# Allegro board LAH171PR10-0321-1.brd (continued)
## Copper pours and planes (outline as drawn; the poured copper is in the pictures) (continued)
GNDA on VCC: 297.22,28.78 296.58,29.41 295.69,29.41 294.64,30.47 294.64,40.18 290.55,44.27 287.37,44.27 286.7,44.95 286.7,46.28 286.23,46.75 282.8,46.75 282.25,47.3 282.25,50.53 282.14,50.65 282.31,50.81 283.64,50.81 284.16,51.33 284.16,52.28 284.21,52.33 287.51,52.33 287.71,52.54 287.71,54.5 287.89,54.68 289.48,54.68 290.56,55.76 292.21,55.76 292.73,56.28 292.73,58.36 292.4,58.68 290.77,58.68 290.39,58.3 289.38,58.3 287.53,56.46 286.69,56.46 286.51,56.64 286.51,57.93 287.08,58.5 287.08,59.77 287.83,60.53 288.01,60.53 288.07,60.59 288.84,60.59 289.47,61.22 292.88,61.22 293.94,60.17 293.94,44.8 298.02,40.71 305.05,40.71 305.98,40.43 306.91,40.71 308.18,40.71 308.63,40.27 314.85,40.27 315.11,39.93 315.46,39.67 309.88,39.67 309.81,39.6 309.81,39.14 309.51,38.83 308.26,38.83 307.96,39.14 307.96,39.57 307.86,39.67 305.35,39.67 303.8,38.63 304.18,36.81 304.18,32.39 303.78,30.62 305.24,29.53 305.32,29.61 305.32,30.05 305.65,30.38 306.89,30.38 307.17,30.1 307.17,29.63 307.27,29.53 317.08,29.53 317.08,28.78
VCC2_IA on BOTTOM: 170.56,131.65 169.98,131.65 169.92,131.58 169.92,131.01 170.24,130.69 170.24,130.5 170.43,130.31 170.43,129.49 170.49,129.42 170.75,129.42 170.81,129.49 170.81,130.12 170.75,130.19 170.75,131.46
VCC3_IA on BOTTOM: 179.26,133.36 178.24,133.36 178.18,133.3 178.18,132.09 178.3,131.96 179.26,131.96 179.57,131.65 179.57,131.14 180.4,130.31 180.4,129.61 180.46,129.55 180.65,129.55 180.72,129.61 180.72,130.69 180.46,130.95 180.46,132.22 180.21,132.47 179.51,132.47 179.38,132.6 179.38,133.23
VCC4_IA on BOTTOM: 190.37,130.95 190.37,129.68 190.3,129.61 190.11,129.61 190.05,129.68 190.05,131.9 189.8,132.15 188.91,132.15 188.84,132.22 188.84,133.36 188.91,133.42 189.92,133.42 190.05,133.3 190.05,132.47 190.11,132.41 190.81,132.41 190.88,132.34 190.88,131.46
VCC_1.05VALWP on BOTTOM (solid shape): 198.05,88.59 198.05,87.44 197.94,87.32 197.18,87.32 197.1,87.4 197.1,87.94 197.24,88.07 197.24,88.35 197.54,88.66 197.99,88.66
VCC_GT on BOTTOM: 100.07,86.37 99.5,86.37 99.44,86.31 99.06,86.31 98.74,85.99 97.47,85.99 97.4,85.93 97.4,85.23 97.21,85.04 96.45,85.04 96.39,84.97 96.39,84.15 96.45,84.08 97.4,84.08 97.47,84.15 97.47,84.59 98.48,85.61 98.86,85.61 99.31,86.05 100.13,86.05 100.2,86.12 100.2,86.24
VCC_SA on BOTTOM: 193.1,121.61 195.58,121.61 196.08,121.1 197.73,121.1 197.99,120.85 197.99,119.14 197.92,119.07 197.8,119.07 197.73,119.14 197.73,120.41 197.54,120.6 195,120.6 194.94,120.53 193.42,120.53 193.04,120.91 193.04,121.55
VDD_CHG on BOTTOM (solid shape): 128.03,38.3 128.03,37.92 127.87,37.77 127.67,37.77 127.57,37.67 126.4,37.67 126.35,37.72 126.35,37.82 126.4,37.87 127.19,37.87 127.72,38.4 127.93,38.4
VDD_CHG on TOP: 139.31,36.08 141.66,36.08 141.79,35.95 141.79,35.32 141.54,35.06 139.12,35.06 139,35.19 139,35.76
VDDP_CHG on BOTTOM (solid shape): 121.9,40.44 121.9,40.32 121.9,40.32 121.9,39.3 121.89,39.29 121.89,38.81 122.43,38.27 123.09,38.27 123.14,38.22 123.14,38.1 123.09,38.05 122.15,38.05 121.46,38.73 121.07,38.73 121,38.8 121,40.57 121.77,40.57
VIN_1.2V_RUN on BOTTOM (solid shape): 270.1,68 270.61,68 270.61,68.58 271.24,68.58 271.44,68.39 271.44,66.61 271.24,66.42 269.78,66.42 269.15,65.78 268.83,65.78 268.64,65.97 268.64,67.45 268.98,67.45 269.67,68.14 269.67,68.58 270.1,68.58
VIN_1.8VALW on TOP (solid shape): 229.92,73.15 229.92,71.07 229.79,70.94 227.87,70.94 227.87,71.35 227.87,71.35 227.32,71.35 227.31,71.36 227.31,71.53 227.32,71.54 227.86,71.54 227.87,71.54 227.87,71.66 227.87,71.96 229.24,73.33 229.73,73.33
VIN_1VS_VCCIO on TOP: 199.39,96.47 199.7,96.15 201.16,96.15 201.29,96.28 201.29,99.77 200.97,100.09 199.7,100.09 199.39,99.77
VIN_1VS_VCCIO on BOTTOM: 198.94,98.31 200.21,98.31 200.59,98.69 201.1,98.69 201.29,98.5 201.29,97.86 201.48,97.67 201.48,96.72 200.91,96.15 200.91,95.51 201.48,95.51 201.48,95.39 200.91,95.39 200.91,94.94 200.85,94.88 200.46,94.88 198.81,96.53 198.81,98.18
VIN_2.5V_MEM on TOP: 149.86,38.26 151.19,38.26 151.38,38.07 151.38,37.39 151.95,37.39 151.95,37.26 151.38,37.26 151.38,36.68 151.07,36.37 150.76,36.37 150.5,36.12 150.5,35.58 150.45,35.53 149.28,35.53 149.16,35.66 149.16,36.04 149.73,36.61 149.73,38.14
+BL_PWR_SRC on BOTTOM (solid shape): 134.74,132.73 134.74,132.23 134.5,131.98 134.27,131.98 133.93,131.65 133.93,130.47 133.85,130.39 132.68,130.39 132.6,130.47 132.6,131.75 132.14,132.21 132.14,132.65 132.27,132.78 134.69,132.78
+BL_PWR_SRC on TOP: 142.87,126.38 142.24,127.01 140.9,127.01 139.12,128.79 137.22,128.79 135.89,130.12 133.03,130.12 132.52,130.63 132.52,132.28 132.65,132.41 133.47,132.41 133.67,132.6 133.67,133.61 133.79,133.73 135.58,133.73 135.63,133.68 135.63,132.47 136.46,131.65 137.35,131.65 138.17,130.82 140.14,130.82 141.73,129.23 143.76,129.23 144.2,128.79 144.2,127.65 143.76,127.2 143.76,126.57 143.57,126.38
+BL_PWR_SRC_P on TOP (solid shape): 134.95,136.74 134.95,136.09 135.5,135.54 135.5,134.57 135.3,134.37 134.01,134.37 133.47,133.83 133.47,132.79 133.28,132.6 132.08,132.6 131.83,132.85 131.83,136.57 132.06,136.8 134.88,136.8
+EDP_VDD on TOP: 145.92,132.73 147.63,132.73 147.7,132.66 147.7,131.2 147.44,130.95 145.92,130.95 145.85,131.01 145.85,131.52 145.28,131.52 145.28,131.65 145.85,131.65 145.85,132.66
+GT_CORE on BOTTOM (solid shape): 147.48,92.65 147.53,92.64 147.57,92.6 147.61,92.34 147.83,92.19 147.86,92.18 147.92,92.18 148.1,92 148.1,91.86 148.07,91.8 148.05,91.74 148,91.68 147.92,91.67 147.67,91.62 147.52,91.4 147.49,91.34 147.42,91.32 147.39,91.32 147.32,91.34 147.28,91.4 146.96,91.67 146.63,91.4 146.6,91.34 146.53,91.32 146.49,91.32 146.45,91.32 146.37,91.33 146.33,91.4 146.01,91.67 145.68,91.4 145.65,91.35 145.58,91.32 145.55,91.32 145.48,91.34 145.44,91.4 145.33,91.6 145.12,91.67 145.09,91.67 145.04,91.72 145.1,91.78 145.1,92.15 145.12,92.18 145.16,92.2 145.2,92.17 145.21,92.16 145.61,92.07 145.79,92.44 145.8,92.53 145.79,92.61 145.82,92.64 145.86,92.65
+GT_CORE on TOP: 115.69,99.07 110.37,99.07 110.08,98.78 110.08,88.94 110.42,88.59 116.2,88.59 117.77,90.16 117.77,91.47 118.07,91.77 118.07,92.15 116.01,94.21 116.01,98.75
+GT_CORE on TOP: outline of 89 points within 133.31,91.06 148.25,109.87
+GT_CORE on BOTTOM: outline of 159 points within 111.95,83.7 148.5,118.95
+GT_CORE on BOTTOM: 141.73,91.24 141.72,91.23 141.66,91.23 141.49,91.06 141.47,91.06 141.24,90.99 141.12,90.79 141.11,90.75 140.89,90.75 140.88,90.78 140.56,91.03 140.24,90.78 140.23,90.75 140,90.75 139.99,90.78 139.95,90.87 139.89,90.95 139.89,91.79 139.47,92.21 139.47,92.55 139.57,92.65 144.47,92.65 144.51,92.64 144.55,92.61 144.54,92.54 144.55,92.47 144.55,92.3 144.64,92.15 144.64,91.97 144.39,91.75 144.51,91.44 144.55,91.35 144.51,91.27 144.44,91.21 144.4,91.13 144.35,91.07 144.28,91.06 144.05,91.02 143.9,90.83 143.9,90.82 143.82,90.75 143.63,90.75 143.62,90.78 143.32,91.03 142.99,90.82 142.99,90.81 142.93,90.75 142.77,90.75 142.66,90.85 142.65,90.85 142.64,90.87 142.5,90.96 142.34,90.97 142.26,90.99 142.22,91.06 142.19,91.16 142.13,91.24 142.13,91.47 142.21,91.59 142.22,91.72 142.22,91.73 141.79,91.94 141.73,91.47
+GT_CORE on IN1: 132.59,109.75 148.29,109.75 148.29,102.93 147.61,102.24 147.61,99.11 146.85,98.35 146.85,97.45 148.29,96.01 148.29,92.59 148.04,92.34 144.06,92.34 143.49,91.77 139.1,91.77 138.91,91.58 137.52,91.58 136.94,92.15 135.12,92.15 134.49,92.78 133.45,92.78 133.33,92.91 133.33,93.29 133.45,93.42 133.86,93.42 134.7,94.26 135.78,94.26 137.56,96.04 137.56,99.43 135.95,101.04 135.95,103.01 134.81,104.15 134.29,104.15 132.4,106.05 132.4,109.56
+GT_CORE on VCC: 112.33,88.19 111.64,88.88 111.64,99.59 115.76,99.59 126.1,109.93 148.62,109.93 148.62,106.61 148.19,106.17 148.19,102.82 147.61,102.24 147.61,99.11 146.85,98.35 146.85,97.45 148.19,96.11 148.19,91.69 120.38,91.69 116.87,88.19
+GT_CORE on IN2: 148.39,110.39 148.39,103.09 147.62,102.32 147.62,99.1 146.85,98.33 146.85,97.45 148.2,96.1 148.2,92.34 147.51,91.64 124.72,91.64 122.31,89.23 118.11,89.23 117.15,88.28 112.26,88.28 111.56,88.97 111.56,96.88 115.66,100.98 115.66,102.59 120.52,107.45 121.92,107.45 126.54,112.08 146.71,112.08
+GT_CORE on IN3: 124.52,109.87 113.91,99.26 113.91,93.61 111.82,91.51 111.82,88.59 112.26,88.15 121.92,88.15 122.55,88.78 122.55,91.77 123.57,92.78 129.66,92.78 130.04,93.16 133.09,93.16 133.47,92.78 139.57,92.78 139.95,92.4 147.51,92.4 148.18,93.08 148.18,96.12 146.84,97.46 146.84,98.33 147.61,99.1 147.61,102.24 148.33,102.96 148.33,109.61 148.08,109.87
+GT_CORE on IN4: 124.52,109.87 113.91,99.26 113.91,93.61 111.82,91.51 111.82,88.59 112.26,88.15 121.92,88.15 126.17,92.4 134.55,92.4 135.25,91.7 147.25,91.7 147.63,92.09 147.63,92.66 147.44,92.85 145.54,92.85 145.09,93.29 145.09,94.12 145.92,94.94 148.08,94.94 148.2,95.06 148.2,96.1 146.85,97.45 146.85,98.35 147.61,99.11 147.61,102.24 148.19,102.82 148.19,106.17 148.33,106.31 148.33,109.61 148.08,109.87
+IA_CORE on TOP (solid shape): 167.69,94.04 167.69,93.58 167.96,93.31 167.96,92.82 168.02,92.4 168.44,92.34 168.47,92.31 168.47,91.92 168.49,91.91 168.49,90.52 168.42,90.45 168.37,90.45 167.53,90.45 167.47,90.52 167.47,91.6 167.17,91.89 167.17,92.48 167.06,92.59 167.06,94.06 167.13,94.12 167.61,94.12
+IA_CORE on TOP: outline of 174 points within 147.35,90.33 187.19,124.72 ; 3 cut-outs
+IA_CORE on BOTTOM: outline of 101 points within 160.45,90.75 168.89,92.73
+IA_CORE on BOTTOM: outline of 376 points within 148.66,102.94 190.94,122.57
+IA_CORE on BOTTOM: outline of 131 points within 149.05,90.32 160.69,92.68
+IA_CORE on IN1: 150.6,119.45 163.13,119.45 163.51,119.83 181.95,119.83 184.06,121.94 185.73,121.94 187.13,120.55 187.13,117.96 186.39,117.22 190.69,117.22 191.07,116.84 191.07,115.31 189.62,113.87 176.51,113.87 173.76,116.62 150.52,116.62 150.2,116.94 150.2,119.05
+IA_CORE on IN1: 159.51,91.13 158.81,91.83 149.65,91.83 149.65,91.83 149.45,91.83 149.26,92.02 149.26,92.21 148.63,92.85 148.63,96.39 147.36,97.66 147.36,98.15 148.12,98.91 148.12,102.03 148.63,102.54 148.63,109.74 165.59,109.74 165.59,107.33 165.54,107.25 165.45,107.24 164.95,106.91 165.45,106.59 165.54,106.58 165.59,106.5 165.59,105.4 165.55,105.32 165.47,105.3 165.46,105.3 165.01,104.96 165.46,104.62 165.47,104.62 165.55,104.6 165.59,104.52 165.59,99.32 167.28,97.63 167.28,93.12 168.19,92.21 168.19,91.32 168,91.13
+IA_CORE on VCC: 155.59,90.24 154.14,91.69 148.7,91.69 148.7,96.33 148.68,96.33 147.35,97.66 147.35,98.14 148.12,98.9 148.12,102.03 148.7,102.61 148.7,105.96 149.13,106.39 149.13,122.12 151.61,124.6 184.88,124.6 191.6,117.88 191.6,114.42 189.65,114.42 188.63,115.44 171.43,115.44 165.82,109.83 165.82,99.33 168,97.15 168,92.7 168.33,92.37 168.33,90.24
+IA_CORE on IN2: 149.23,91.08 148.72,91.59 148.72,96.31 147.35,97.68 147.35,98.15 148.12,98.92 148.12,102.02 148.62,102.52 148.62,117.45 153.16,121.99 186.49,121.99 191,117.49 191,115.14 189.61,113.74 177.41,113.74 166.27,102.59 166.27,94.17 168.17,92.26 168.17,91.48 167.77,91.08
+IA_CORE on IN3: 149.98,90.24 148.69,91.54 148.69,96.33 147.35,97.66 147.35,98.14 148.12,98.9 148.12,102.03 148.69,102.61 148.69,109.72 149.22,110.25 165.35,110.25 166.17,109.42 166.17,92.28 164.97,91.07 158.87,91.07 158.05,90.24
+IA_CORE on IN3: 150.87,119.64 181.61,119.64 183.89,121.93 186.37,121.93 187.26,121.04 187.26,118.95 188.72,117.49 190.69,117.49 191,117.17 191,115.9 190.18,115.07 190.11,115.07 189.73,114.69 187.96,114.69 186.05,116.6 150.43,116.6 150.05,116.98 150.05,118.82
+IA_CORE on IN4: 151.09,120.62 183.12,120.62 184.34,121.84 188.88,121.84 191.65,119.07 191.65,115.59 189.92,113.87 177.96,113.87 175.29,116.53 166.94,116.53 166.85,116.62 165.41,116.62 165.3,116.72 160.21,116.72 160.1,116.62 150.7,116.62 150.63,116.69 150.63,120.17
+IA_CORE on IN4: 149.09,94.31 148.7,94.7 148.7,96.31 147.36,97.66 147.36,98.09 147.35,98.14 148.12,98.91 148.12,102.03 148.59,102.5 148.59,109.17 149.28,109.87 165.54,109.87 165.92,109.48 165.92,95.01 165.22,94.31
+LCDVDD on TOP (solid shape): 145.25,134.98 145.25,132.69 145.66,132.28 145.66,131.84 145.09,131.84 145.09,131.33 145.66,131.33 145.66,129.39 145.54,129.26 144.97,129.26 144.78,129.45 144.78,130.67 144.28,131.16 142.15,131.16 142,131.01 139.95,131.01 139.76,131.2 139.76,132.28 139.89,132.42 141.02,132.42 141.61,133.01 141.61,133.15 142.59,134.13 142.59,134.81 142.77,134.99 145.24,134.99
+LCDVDD on BOTTOM (solid shape): 140.9,132.4 140.9,132.03 140.77,131.9 140.04,131.9 139.91,131.77 139.91,130.42 139.87,130.38 139.14,130.38 139.11,130.41 139.11,132.45 139.26,132.59 140.71,132.59
+MIC2-VREFO on TOP (solid shape): 287.98,53.49 289.26,53.49 289.52,53.23 289.52,52.92 289.47,52.87 289.15,52.87 288.77,53.25 287.8,53.25 287.72,53.33 287.72,53.43 287.78,53.5 287.97,53.5
+MIC2-VREFO on IN3 (solid shape): 296.92,33.41 296.92,31.38 296.79,31.25 295.91,31.25 295.71,31.44 295.71,33.47 295.91,33.67 296.67,33.67
+MIC2-VREFO on BOTTOM: 296.73,33.22 296.1,33.22 296.03,33.16 296.03,32.59 295.78,32.33 295.78,31.95 295.97,31.76 295.97,30.68 296.03,30.62 296.67,30.62 296.73,30.68 296.73,31.76 296.92,31.95 296.92,32.33 296.79,32.46 296.79,33.16
+REGCTL_PNP10 on TOP (solid shape): 276.27,110.79 276.27,109.34 276.87,108.75 277.1,108.75 277.55,108.3 277.55,107.73 277.4,107.58 276.15,107.58 276.09,107.65 276.09,107.65 276.05,107.69 276.05,110.77 276.12,110.84 276.22,110.84
+RTC_CELL_PCH on TOP: 280.77,101.38 280.77,100.66 282.61,98.82 282.61,98.19 282.81,98 283.51,98 284.4,98.88 284.4,100.96 284.31,101.05 282.69,101.05 282.31,101.43 280.83,101.43
+RTC_CELL_PCH on TOP: 244.6,109.8 244.03,109.8 243.9,109.67 243.9,109.29 243.84,109.23 243.27,109.23 243.21,109.29 243.21,110.72 243.57,111.08 243.57,112.73 243.64,112.8 244.19,112.8 244.22,112.77 244.26,112.73 244.32,112.7 244.72,112.29 244.72,109.93
+SA_CORE on TOP: 187.64,110.82 187.64,108.4 188.15,107.9 197.29,107.9 197.48,108.09 197.48,110.94 197.23,111.2 188.02,111.2
+SA_CORE on TOP: 166.57,100.05 166.42,100.2 166.42,103.37 166.28,103.51 165.75,103.51 165.65,103.61 165.65,104.21 165.71,104.28 166.15,104.28 166.28,104.4 166.28,106.4 166.18,106.5 166.18,109.75 166.56,110.12 168.4,110.12 168.63,109.89 168.63,106.5 168.43,106.3 168.43,103.46 168.37,103.4 167.36,103.4 167.18,103.22 167.18,102.74 167.11,102.66 167.11,101.34 167.34,101.11 168.11,101.11 168.58,101.59 169.06,101.59 169.11,101.53 169.11,100.43 168.73,100.05
+SA_CORE on BOTTOM: 166.54,103.2 166.32,103.42 166.32,108.81 166.46,108.96 166.49,108.96 166.72,109.06 166.74,109.31 166.73,109.32 166.73,109.72 166.74,109.73 166.76,109.82 166.75,109.92 164.65,112.02 164.65,113.23 164.71,113.29 167.32,113.29 167.93,112.68 167.93,108.4 168.06,108.28 168.38,108.28 168.63,108.02 168.63,105.04 169.01,104.66 169.01,103.96 168.25,103.2
+SA_CORE on BOTTOM: 187.64,110.82 187.64,108.28 187.96,107.96 194.43,107.96 194.5,108.02 194.5,109.1 194.37,109.23 193.48,109.23 193.42,109.29 193.42,110.12 193.54,110.25 194.46,110.25 194.46,111.1 194.43,111.14 187.96,111.14
+SA_CORE on IN1: 166.37,109.62 166.37,102.88 166.47,102.78 167.82,102.78 168.15,103.11 168.15,109.48 167.9,109.74 166.49,109.74
+SA_CORE on VCC: 173.65,100.09 172.31,101.42 170.09,101.42 168.69,102.82 166.33,102.82 166.33,109.62 171.64,114.93 188.42,114.93 189.44,113.92 191.75,113.92 193.51,112.16 193.51,104.52 189.16,104.52 187.64,103 187.64,100.09
+SDREG2 on TOP: 295.97,27.07 296.35,27.07 296.4,27.02 296.4,26.44 296.53,26.31 296.53,24.99 296.35,24.81 295.54,24.81 295.49,24.86 295.49,24.99 295.71,25.22 295.71,25.91 295.94,26.13 295.94,27.05
+TBT_SVR_IND on BOTTOM: 38.13,111.68 38.05,111.6 38.05,111.44 38,111.39 37.78,111.39 37.7,111.47 37.7,111.64 37.62,111.72 37.62,112.17 37.45,112.35 37.44,112.35 37.4,112.4 36.8,112.4 36.45,112.75 35.75,112.75 35.62,112.62 35.62,110.66 35.37,110.4 33.91,110.4 33.59,110.72 33.59,113.96 34.53,114.9 36.49,114.9 37.51,113.88 38.17,113.88 38.17,113.88 38.17,113.54 38.17,113.53 38.17,113.43 38.18,113.41 38.18,113.13 38.32,112.99 38.32,112.13 38.34,112.12 38.34,111.8 38.28,111.75 38.23,111.74 38.18,111.73
+TS_PWR on TOP (solid shape): 126.11,132.41 126.11,130.12 125.79,129.8 124.07,129.8 123.63,130.25 123.63,131.9 123.76,132.03 124.96,132.03 125.41,132.47 126.04,132.47
+TS_PWR_QV8 on TOP (solid shape): 123.69,135.07 123.69,132.41 123.44,132.15 123.44,131.26 122.93,130.76 122.23,130.76 121.98,131.01 121.98,135.27 122.11,135.39 123.38,135.39
+USB_EX2_PWR on BOTTOM (solid shape): 21.05,97.23 21.12,97.2 21.15,97.13 21.19,96.96 21.29,96.84 21.33,96.77 21.31,96.69 21.34,96.2 21.83,96.21 21.9,96.24 21.97,96.21 22,96.19 22.03,96.17 22.03,94.81 22.02,94.82 20.9,94.82 20.89,94.81 20.66,94.81 20.55,94.69 18,94.69 16.87,93.56 15.74,93.56 15.49,93.81 15.49,95.13 17.58,97.23
+USB_EX2_PWR on BOTTOM: 23.11,88.59 24,88.59 24.25,88.34 24.25,86.69 23.74,86.18 22.03,85.42 19.11,85.42 18.85,85.67 18.85,87.7 19.11,87.96 20.19,87.96 20.63,87.51 22.86,87.51 22.98,87.64 22.98,88.47
+USB_EX2_PWR on IN1: 17.84,85.8 17.14,86.5 17.14,91.78 15.46,93.46 15.46,95.27 16.19,96 19.71,96 20.12,95.58 20.12,86.05 19.87,85.8
+USB_EX3_PWR on TOP (solid shape): 301.43,50.68 301.43,47.84 302.12,47.15 302.55,47.15 303.59,46.11 303.59,45.1 303.4,44.9 302.64,44.9 301.94,45.6 299.33,45.6 299.21,45.48 298.31,45.48 298.2,45.58 298.2,46.21 299.27,47.28 299.27,50.68 299.52,50.94 301.18,50.94
+UZ12_TPM on TOP: 246.63,127.65 247.45,127.65 247.9,127.2 250.19,127.2 250.31,127.07 250.31,126.5 250.25,126.44 249.23,126.44 249.04,126.63 248.15,126.63 247.52,127.26 246.69,127.26 246.57,127.39 246.57,127.58
+VHDMI_VCC on TOP: 301.18,82.62 304.1,82.62 304.22,82.5 304.22,81.54 303.91,81.23 303.33,81.23 303.02,81.54 301.24,81.54 301.05,81.73 301.05,82.5
+VHDMI_VCC on TOP: 295.89,81.91 295.89,81.05 295.71,80.87 292.64,80.87 292.54,80.97 292.54,81.99 292.67,82.12 294.06,82.12 294.46,82.51 294.46,82.86 294.85,83.26 296.03,83.26 296.16,83.13 296.16,82.18
+VHDMI_VCC on IN2: 303.14,82.56 303.91,82.56 304.86,81.61 306.13,81.61 306.38,81.35 306.38,80.78 306.19,80.59 303.97,80.59 303.02,81.54 303.02,82.43
+VR_CAP on TOP (solid shape): 261.5,94.67 261.5,94.41 261.38,94.29 261.01,94.29 260.48,93.76 260.03,93.76 259.85,93.58 259.85,93.38 259.75,93.27 259.53,93.27 259.16,93.65 258.77,93.65 258.64,93.78 258.64,94.22 258.77,94.35 259.98,94.35 260.37,94.75 260.71,94.75 260.71,94.75 261.42,94.75
ADP_CHG on BOTTOM (solid shape): 129.28,40.02 129.28,39.13 129.2,39.05 127.1,39.05 126.66,38.6 126.46,38.6 126.24,38.38 126.08,38.38 126.03,38.43 126.03,39.19 126.08,39.24 126.61,39.24 127.01,39.63 128.07,39.63 128.58,40.14 129.15,40.14
AUD_HP_NB_SENSE on IN1 (solid shape): 309.94,30.17 309.94,28.93 309.79,28.78 308.19,28.78 308.08,28.88 308.08,30.15 308.31,30.38 309.74,30.38
AUD_HP_OUT_L1 on BOTTOM (solid shape): 307.22,40.51 307.22,39.06 307.04,38.89 305.39,38.89 305.21,39.06 305.21,40.5 305.3,40.59 307.14,40.59
AUD_HP_OUT_R1 on TOP (solid shape): 312.68,30.25 312.68,29.06 312.48,28.85 310.9,28.85 310.78,28.98 310.78,30.22 310.93,30.38 312.56,30.38
BGATE_CHG on TOP: 115.63,39.32 117.28,39.32 117.41,39.19 117.41,38.17 117.15,37.92 115.82,37.92 115.5,38.24 115.5,39.19
BOOT1_CHG on BOTTOM (solid shape): 124.95,40.69 124.95,39.52 124.66,39.23 124.66,38.43 124.61,38.38 124.48,38.38 124.43,38.43 124.43,39.47 124.52,39.56 124.52,40.28 124.09,40.71 122.99,40.71 122.93,40.78 122.93,41.41 122.99,41.48 124.17,41.48
BOOT2_CHG on BOTTOM (solid shape): 123.14,36.62 123.14,36.5 123.11,36.47 122.17,36.47 121.02,35.32 120.52,35.32 120.46,35.37 120.46,36.34 120.52,36.4 121,36.4 121.44,36.4 121.59,36.55 121.97,36.55 122.1,36.67 123.09,36.67
BS_DDR on TOP: 173.16,39 173.86,39 174.05,38.81 174.05,37.48 173.92,37.35 173.22,37.35 173.1,37.48 173.1,38.94
BS_DDR on BOTTOM: 173.73,39 174.05,38.68 174.05,37.73 173.99,37.67 173.73,37.67 173.29,38.11 173.29,38.94 173.35,39
BS_DDR_R on TOP: 171,38.55 172.52,38.55 172.59,38.49 172.59,37.48 172.46,37.35 170.87,37.35 170.75,37.48 170.75,38.3
BST1_CHG_R on BOTTOM: 123.82,42.94 122.11,42.94 121.92,42.75 121.92,41.98 122.04,41.86 123.69,41.86 123.95,42.11 123.95,42.81
BST2_CHG_R on BOTTOM: 119.15,37 119.98,37 120.14,36.84 120.14,35.25 120.01,35.13 119.47,35.13 119.09,35.51 119.09,36.94
BST2_IA on BOTTOM: 171.51,130.19 171.45,130.12 171.45,129.55 171.51,129.49 171.76,129.49 171.83,129.55 171.83,130.38 171.95,130.5 171.95,131.65 171.89,131.71 171,131.71 170.94,131.65 170.94,131.07 171,131.01 171.45,131.01 171.51,130.95
BST2_IA_R on BOTTOM: 170.97,133.14 170.91,133.07 170.91,132.5 171.35,132.06 172.81,132.06 172.87,132.12 172.87,132.63 172.37,133.14
BST3_IA on BOTTOM: 181.61,131.84 180.65,131.84 180.59,131.77 180.59,131.07 180.65,131.01 181.29,131.01 181.41,130.88 181.41,130.38 181.35,130.31 181.35,129.55 181.41,129.49 181.67,129.49 181.73,129.55 181.73,131.01 181.67,131.07 181.67,131.77
BST3_IA_R on BOTTOM: 180.59,133.17 180.53,133.11 180.53,132.53 180.97,132.09 182.43,132.09 182.49,132.15 182.49,132.66 181.99,133.17
BST4_IA on BOTTOM: 192.02,132.03 191.19,132.03 191.13,131.96 191.13,130.5 191.07,130.44 191.07,129.68 191.13,129.61 191.26,129.61 191.32,129.68 191.32,130.25 192.15,131.07 192.15,131.9
BST4_IA_R on BOTTOM: 192.91,133.36 191.19,133.36 191.13,133.3 191.13,132.34 191.26,132.22 192.97,132.22 193.04,132.28 193.04,133.23
BST_1.05VALWP on BOTTOM (solid shape): 197.2,85.7 197.2,85.04 197.21,85.02 197.21,83.75 197.16,83.7 196.34,83.7 196.27,83.77 196.27,84.46 196.79,84.99 196.79,85.85 196.85,85.9 197,85.9
BST_1.05VALWP_R on BOTTOM (solid shape): 198.05,83 198.05,82.37 197.99,82.31 196.31,82.31 196.26,82.35 196.26,83.02 196.31,83.07 197.99,83.07
BST_3V on BOTTOM: 249.96,47.76 249.96,48.4 249.9,48.46 248.63,48.46 248.5,48.34 247.61,48.34 247.55,48.27 247.55,48.15 247.61,48.08 248.5,48.08 248.88,47.7 249.9,47.7
BST_3V_R on BOTTOM: 249.92,49.1 249.07,49.1 249.01,49.16 249.01,49.83 249.39,50.21 249.39,50.87 249.5,50.98 249.91,50.98 250.02,50.87 250.02,49.2
BST_5V on TOP: 200.34,35.19 201.16,35.19 201.67,34.68 201.67,33.79 201.61,33.73 200.46,33.73 200.21,33.98 200.21,35.06
BST_5V on BOTTOM: 200.02,35.25 200.15,35.25 200.27,35.13 200.72,35.13 200.85,35 200.85,34.17 200.72,34.05 200.15,34.05 199.96,34.24 199.96,35.19
BST_5V_R on TOP: 202.43,35.7 203.07,35.7 203.13,35.63 203.13,33.86 203,33.73 202.43,33.73 202.31,33.86 202.31,35.57
BST_GT on BOTTOM: 100.13,87.32 99.5,87.32 99.44,87.39 98.61,87.39 98.48,87.26 98.04,87.26 97.91,87.13 97.91,86.24 97.98,86.18 98.61,86.18 98.67,86.24 98.67,86.94 98.8,87.07 99.25,87.07 99.31,87.01 100.13,87.01 100.2,87.07 100.2,87.26
BST_GT_R on BOTTOM: 97.34,88.08 96.52,88.08 96.45,88.02 96.45,86.24 96.58,86.12 97.34,86.12 97.47,86.24 97.47,87.96
BST_SA_R on TOP: 200.02,122.69 198.75,122.69 198.69,122.63 198.69,121.93 199.13,121.49 200.59,121.49 200.66,121.55 200.66,122.06
CBP on TOP: 288.54,57.1 288.92,57.1 288.98,57.03 288.98,56.72 288.86,56.59 288.86,56.33 288.6,56.08 287.78,56.08 287.71,56.14 287.71,56.27 287.78,56.33 288.35,56.33 288.48,56.46 288.48,57.03
DCIN_CHG on BOTTOM (solid shape): 127.57,38.78 127.57,38.45 127.16,38.05 126.4,38.05 126.35,38.1 126.35,38.22 126.55,38.43 126.73,38.43 127.21,38.91 127.44,38.91
EN_1.8VALW on TOP (solid shape): 231.8,75.81 231.8,74.82 230.6,73.62 229.12,73.62 228.81,73.31 226.1,73.31 226.04,73.37 226.04,73.95 226.19,74.1 228.63,74.1 228.7,74.17 228.7,74.17 229.08,74.17 229.3,74.39 229.3,74.4 229.57,74.4 229.94,74.08 230.29,74.43 230.92,75.07 230.92,75.71 231.14,75.93 231.68,75.93
FB_1.8VALW on TOP (solid shape): 234.07,75.16 234.07,74.69 233.95,74.57 233.5,74.57 233.24,74.32 233.24,73.01 232.47,72.23 231.18,72.23 231,72.41 231,73.64 232.6,75.24 233.99,75.24
INT_SPK_L+ on TOP (solid shape): 286.25,60.41 286.25,58.63 285.94,58.32 285.94,56.54 285.9,56.51 285.76,56.51 285.7,56.56 285.7,58.59 285.56,58.73 285.56,60.48 286.19,60.48
INT_SPK_L+ on TOP (solid shape): 293.24,36.71 293.24,36.33 292.92,36.01 292.92,35.57 292.86,35.51 292.22,35.51 292.1,35.63 292.1,36.65 292.22,36.78 293.17,36.78
INT_SPK_L+ on IN4 (solid shape): 293.3,36.65 293.3,32.84 293.11,32.65 292.54,32.65 292.1,33.09 292.1,36.65 292.16,36.71 293.24,36.71
INT_SPK_L+ on IN4 (solid shape): 285.49,62.44 285.49,61.55 286.32,60.73 286.32,58.76 286.25,58.7 285.68,58.7 285.55,58.82 285.55,60.48 284.48,61.55 284.48,62.38 284.79,62.7 285.24,62.7
INT_SPK_L- on TOP (solid shape): 290.77,36.14 290.77,35.38 290.65,35.25 289.76,35.25 289.63,35.38 289.63,36.14 289.76,36.27 290.65,36.27
INT_SPK_L- on TOP (solid shape): 285.33,60.41 285.33,58.77 285.53,58.56 285.53,56.53 285.5,56.5 285.36,56.5 285.32,56.55 285.32,58.15 284.65,58.81 284.65,60.4 284.73,60.48 285.26,60.48
INT_SPK_L- on IN4 (solid shape): 290.63,36.14 290.63,34.17 290.38,33.92 289.75,33.92 289.49,34.17 289.49,36.33 289.62,36.46 290.32,36.46
INT_SPK_L- on IN4 (solid shape): 285.3,60.41 285.3,58.82 285.17,58.7 284.79,58.7 284.73,58.76 284.73,59.97 283.09,61.61 282,61.61 281.81,61.8 281.81,62.79 281.87,62.85 282.86,62.85
INT_SPK_R+ on TOP (solid shape): 288.55,36.14 288.55,35.38 288.42,35.25 287.53,35.25 287.41,35.38 287.41,36.14 287.53,36.27 288.42,36.27
INT_SPK_R+ on TOP (solid shape): 283.52,60.41 283.52,58.92 283.89,58.55 284.08,58.55 284.74,57.89 284.74,56.54 284.69,56.5 284.55,56.5 284.52,56.53 284.52,57.63 283.83,58.32 283.55,58.32 282.89,58.97 282.89,60.48 283.46,60.48
INT_SPK_R+ on IN4 (solid shape): 283.52,59.71 283.52,58.82 283.4,58.7 282,58.7 281.87,58.82 281.87,59.59 282,59.71 283.01,59.71 283.14,59.84 283.4,59.84
INT_SPK_R+ on IN4 (solid shape): outline of 108 points within 287.27,35.16 289.56,38.94
INT_SPK_R- on TOP (solid shape): 287.46,37.6 287.46,36.51 287.19,36.24 286.43,36.24 286.25,36.42 286.25,37.6 286.32,37.67 287.4,37.67
INT_SPK_R- on TOP (solid shape): 284.48,60.41 284.48,58.78 285.13,58.13 285.13,56.54 285.09,56.5 284.96,56.5 284.9,56.56 284.9,57.94 284.14,58.7 283.93,58.7 283.79,58.84 283.79,60.42 283.84,60.48 284.41,60.48
INT_SPK_R- on IN4 (solid shape): 287.33,37.54 287.33,36.78 287.08,36.52 285.36,36.52 285.24,36.65 285.24,37.48 285.43,37.67 287.21,37.67
INT_SPK_R- on IN4 (solid shape): 284.35,60.09 284.35,58.82 284.22,58.7 284.03,58.7 283.84,58.89 283.84,59.71 283.33,60.22 282,60.22 281.87,60.35 281.87,61.11 282,61.24 283.21,61.24
INT_SPKR_L+ on TOP (solid shape): 293.92,35.95 293.92,34.68 293.54,34.3 293.54,33.16 293.87,32.83 293.87,29.54 293.75,29.41 293.11,29.41 292.98,29.54 292.98,32.27 292.35,32.9 292.35,34.76 293.16,35.57 293.16,35.95 293.29,36.08 293.8,36.08
INT_SPKR_L+ on BOTTOM: 293.37,30.43 293.37,27.35 293.49,27.22 294,27.22 294.25,27.47 294.25,29.54 293.94,29.86 293.94,30.43 293.81,30.55 293.49,30.55
INT_SPKR_L- on TOP (solid shape): 291.7,35.95 291.7,32.95 291.27,32.52 291.27,30.49 291.46,30.3 292.29,30.3 292.54,30.55 292.73,30.55 292.86,30.43 292.86,29.6 292.67,29.41 290.63,29.41 290.32,29.73 290.32,33.24 290.49,33.41 290.49,34.87 290.94,35.31 290.94,35.95 291.07,36.08 291.57,36.08
INT_SPKR_L- on BOTTOM: 292.16,30.24 292.16,27.35 292.29,27.22 292.79,27.22 293.05,27.47 293.05,30.36 292.86,30.55 292.48,30.55
INT_SPKR_R+ on TOP: 288.79,32.46 288.79,30.81 289,30.6 289,29.49 289.07,29.41 289.87,29.41 289.94,29.47 289.94,30.55 289.81,30.68 289.81,33.22 289.8,33.22 289.6,33.41 289.6,34.44 289.36,34.68 289.36,35.95 289.24,36.08 288.84,36.08 288.72,35.95 288.72,35.25 288.47,35 288.47,32.78
INT_SPKR_R+ on BOTTOM: 290.89,29.09 290.89,27.35 291.02,27.22 291.52,27.22 291.78,27.47 291.78,29.73 290.95,30.55 289.43,30.55 289.36,30.49 289.36,29.6 289.62,29.35 290.63,29.35
INT_SPKR_R- on TOP (solid shape): 287.19,35.88 287.19,35 287.65,34.54 287.65,33.47 287.45,33.27 287.45,30.5 287.59,30.36 288.22,30.36 288.41,30.55 288.6,30.55 288.79,30.36 288.79,29.54 288.67,29.41 286.89,29.41 286.29,30.01 286.29,35.75 286.56,36.01 287.06,36.01
INT_SPKR_R- on BOTTOM: 290.25,27.19 290.51,27.44 290.51,28.97 290.32,29.16 289.62,29.16 289.11,29.66 289.11,30.36 288.92,30.55 288.35,30.55 288.16,30.36 288.16,27.32 288.29,27.19
LCDVDD_MONITOR on TOP: 131.33,122.57 131.33,121.98 131.49,121.82 132.82,121.82 133.85,122.84 133.85,123.49 133.78,123.57 133.23,123.57 132.46,122.79 131.55,122.79
LDO_3V on BOTTOM: 246.09,48.53 246.09,49.35 245.77,49.67 245.77,49.99 245.64,50.11 243.2,50.11 243.07,49.99 243.07,47.7 243.14,47.64 243.71,47.64 243.77,47.7 243.77,48.52 243.9,48.65 245.13,48.65 245.39,48.4 245.96,48.4
LG1_CHG on BOTTOM (solid shape): 122.87,39.29 123.35,39.29 123.45,39.19 123.45,38.43 123.4,38.38 123.23,38.38 123,38.6 122.59,38.6 122.16,39.04 122.16,39.37 122.26,39.47 122.69,39.47
LG1_CHG on IN4 (solid shape): 122.4,40.19 122.4,39.87 123.16,39.11 123.16,38.73 122.97,38.54 122.34,38.54 121.28,39.6 121.28,40.33 121.41,40.46 122.13,40.46
LG1_CHG on BOTTOM: 97.42,37.79 97.61,37.6 97.61,36.65 97.42,36.46 96.13,36.46 95.82,36.78 95.82,37.59 96.02,37.79
LG1_CHG on IN4: 96.07,37.92 96.96,37.92 97.09,37.79 97.09,36.14 96.9,35.95 96.01,35.95 95.82,36.14 95.82,37.67
LG2_CHG on BOTTOM (solid shape): 122.12,37.87 123.11,37.87 123.16,37.82 123.16,37.72 123.11,37.67 122.25,37.67 122.2,37.61 121.56,37.61 121.11,38.07 121.11,38.38 121.21,38.48 121.51,38.48
LG2_CHG on TOP: 111.25,31.32 109.34,31.32 109.15,31.13 109.15,29.6 109.28,29.47 110.55,29.47 110.61,29.54 110.61,30.55 110.68,30.62 111.25,30.62 111.31,30.68 111.31,31.25
LG2_CHG on IN4: 122.11,38.3 122.11,37.73 121.85,37.48 121.15,37.48 120.14,38.49 120.14,39 120.39,39.25 121.15,39.25
LG2_CHG on IN4: 109.02,29.42 108.71,29.73 108.71,30.68 108.9,30.87 110.61,30.87 110.87,30.62 110.87,29.73 110.56,29.42
LX1_CHG on BOTTOM (solid shape): 122.68,41.6 122.68,40.78 122.8,40.65 122.8,40.65 123.12,40.33 123.12,40.33 123.86,39.6 123.86,38.41 123.82,38.38 123.67,38.38 123.65,38.4 123.65,39.19 123.39,39.44 123.12,39.44 121.98,40.59 121.98,41.54 122.11,41.67 122.61,41.67
LX1_CHG on IN1 (solid shape): 123.67,39.81 123.67,39.43 123.54,39.3 123.04,39.3 122.7,39.63 121.6,39.63 121.41,39.82 121.41,40.9 121.47,40.97 122.51,40.97
LX1_CHG on TOP: 100.96,36.14 103.41,36.14 103.74,35.81 103.74,34.49 103.42,34.17 100.96,34.17 100.83,34.3 100.83,36.01
LX1_CHG on BOTTOM: 110.68,43.7 111.06,43.32 111.06,36.52 110.8,36.27 105.66,36.27 105.21,35.82 105.21,32.33 104.83,31.95 98.18,31.95 98.01,32.12 98.01,37.63 98.17,37.79 102.99,37.79 103.18,37.98 103.18,39.51 102.99,39.7 101.15,39.7 100.9,39.95 100.9,43.38 101.21,43.7
LX1_CHG on IN1: 102.6,34.69 102.6,36.28 102.92,36.6 103.68,36.6 104.12,36.15 104.12,34.76 103.93,34.57 102.73,34.57
LX1_IA on TOP: 163.13,123.77 161.54,123.77 161.48,123.71 161.48,121.1 161.67,120.91 162.87,120.91 163.25,121.3 163.25,123.64
LX1_IA on BOTTOM: 159.25,126.76 157.92,126.76 157.79,126.63 157.79,124.72 157.54,124.47 155.95,124.47 155.7,124.22 155.7,120.72 155.82,120.6 157.98,120.6 158.05,120.53 158.05,119.71 157.16,119.71 156.97,119.52 156.97,118.44 157.03,118.37 160.78,118.37 161.09,118.69 162.49,118.69 162.87,119.07 162.87,123.33 163.32,123.77 163.32,125.17 163.19,125.3 159.44,125.3 159.32,125.42 159.32,126.69
LX2_CHG on BOTTOM (solid shape): 121.44,37.49 123.11,37.49 123.16,37.44 123.16,37.31 123.11,37.26 120.93,37.26 120.81,37.14 119.33,37.14 119.06,37.41 119.06,38.24 119.12,38.3 120.62,38.3
LX2_CHG on TOP: 108.33,36.14 105.72,36.14 105.7,36.12 105.21,36.12 104.83,35.74 104.83,34.24 103.06,32.46 103.06,30.49 103.44,30.11 106.68,30.11 108.26,31.7 110.1,31.7 110.29,31.89 110.29,35.06 110.17,35.19 109.28,35.19
LX2_CHG on TOP: 116.26,32.9 115.06,32.9 114.99,32.84 114.99,31.76 115.06,31.7 116.14,31.7 116.33,31.89 116.33,32.84
LX2_CHG on BOTTOM: 105.14,31.87 104.96,31.7 103.5,31.7 103.18,31.38 103.18,30.36 103.37,30.17 110.42,30.17 110.55,30.3 110.55,35.7 110.29,35.95 105.79,35.95 105.76,35.93 105.46,35.93 105.14,35.61
LX2_CHG on IN1: 114.99,36.21 117.22,38.43 121.06,38.43 121.25,38.24 121.25,37.48 121.06,37.28 118.93,37.28 117.85,36.21 117.85,33.54 116.07,31.76 115.57,31.76 114.68,30.87 107.63,30.87 106.99,30.24 103.44,30.24 103.12,30.55 103.12,32.4 104.83,34.11 104.83,35.71 105.33,36.21
LX2_IA on TOP: 172.84,122.69 171.19,122.69 171.06,122.57 171.06,121.04 171.19,120.91 172.97,120.91 173.03,120.98 173.03,122.5
LX2_IA on BOTTOM: 169.29,126.76 168.08,126.76 167.95,126.63 167.95,120.79 168.08,120.66 170.94,120.66 170.94,119.77 169.92,119.77 169.79,119.64 169.79,118.31 169.92,118.18 172.65,118.18 173.03,118.56 173.03,122.69 173.6,123.26 173.6,125.04 173.41,125.23 169.48,125.23 169.35,125.36 169.35,126.69
LX3_IA on TOP: 182.11,122.76 180.53,122.76 180.4,122.63 180.4,120.91 180.46,120.85 182.24,120.85 182.37,120.98 182.37,122.5
LX3_IA on BOTTOM: 179.26,126.88 177.99,126.88 177.86,126.76 177.86,122.12 179.26,120.72 181.41,120.72 181.41,119.77 180.53,119.77 180.4,119.64 180.4,118.56 180.53,118.44 183.07,118.44 183.45,118.82 183.45,125.17 183.26,125.36 179.51,125.36 179.32,125.55 179.32,126.82
LX4_IA on TOP: 194.37,125.55 192.65,125.55 192.59,125.49 192.59,123.9 192.72,123.77 194.24,123.77 194.43,123.96 194.43,125.49
LX4_IA on BOTTOM: 188.84,126.95 188.08,126.95 187.7,126.57 187.7,125.49 186.18,123.96 186.18,120.91 186.37,120.72 187.38,120.72 187.51,120.85 187.51,121.87 188.34,121.87 188.34,120.66 188.46,120.53 189.67,120.53 189.86,120.72 189.86,122.06 190.3,122.5 193.67,122.5 193.99,122.82 193.99,124.66 193.23,125.42 188.97,125.42 188.91,125.49 188.91,126.88
LX_1.05VALWP on TOP (solid shape): 201.86,86.81 201.86,85.61 201.54,85.29 193.48,85.29 193.35,85.42 193.35,86.05 193.48,86.18 199.26,86.18 199.96,86.88 201.8,86.88
LX_1.05VALWP on BOTTOM (solid shape): 194.88,86.18 194.88,86.05 194.56,85.74 194.56,85.61 194.31,85.36 193.58,85.36 193.39,85.55 193.39,85.86 193.77,86.24 194.81,86.24
LX_1.05VALWP on BOTTOM (solid shape): 203,86.56 203,83.51 202.94,83.45 198.31,83.45 198.18,83.32 197.48,83.32 197.42,83.39 197.42,85.77 197.13,86.06 197.13,86.59 197.22,86.69 202.88,86.69
LX_1.8VALW on TOP (solid shape): 229.93,78.5 229.93,77.39 229.74,77.19 229.74,76.81 229.93,76.62 229.93,75.11 229.71,74.88 229.19,74.88 229,75.07 229,75.68 228.35,76.34 228.35,77.43 228.15,77.63 227.14,77.63 226.85,77.93 226.85,78.67 227.18,79.01 229.43,79.01
LX_1VS_VCCIO on BOTTOM: 196.59,98.37 195.45,98.37 194.43,99.39 193.35,99.39 193.23,99.51 193.23,100.28 193.16,100.34 191.77,100.34 191.51,100.09 191.51,97.48 191.64,97.36 195.45,97.36 195.58,97.48 196.53,97.48 196.65,97.61 196.65,98.31
LX_3V on TOP: 247.07,50.94 249.3,50.94 249.49,50.75 249.49,49.67 249.3,49.48 247.14,49.48 246.95,49.67 246.95,50.81
LX_3V on BOTTOM: 247.17,46.11 247.17,44.78 247.23,44.72 247.93,44.72 248.05,44.84 248.05,46.05 247.99,46.11 247.48,46.11 247.42,46.18 247.23,46.18
LX_3V on BOTTOM: 248.8,53.61 244.17,53.61 244.05,53.49 244.05,50.82 244.16,50.72 246.63,50.72 246.72,50.62 246.72,48.53 246.78,48.46 248.18,48.46 248.69,48.97 248.69,49.82 249.18,50.32 249.18,53.23
LX_3V on IN4: 248.12,50.49 248.12,44.97 247.93,44.78 247.17,44.78 247.04,44.91 247.04,50.49 247.17,50.62 247.99,50.62
LX_5V on TOP: 201.29,35.76 201.29,35.32 201.73,34.87 201.99,34.87 202.18,35.06 202.18,35.7 202.37,35.89 203.07,35.89 203.39,35.57 205.1,35.57 205.23,35.7 205.23,36.97 205.1,37.09 202.62,37.09
LX_5V on BOTTOM: 200.34,36.01 204.15,36.01 204.66,35.51 205.8,35.51 207.83,33.47 208.97,33.47 209.48,32.97 209.48,30.55 209.44,30.52 204.29,30.52 203.39,31.42 203.39,33.16 201.29,35.25 200.4,35.25 200.27,35.38 200.27,35.95
LX_5V on BOTTOM: 198.05,35.57 196.91,35.57 196.72,35.38 196.72,34.81 196.85,34.68 197.67,34.68 197.8,34.81 197.8,35 198.12,35.32 198.12,35.51
LX_5V on IN1: 201.99,36.01 197.48,36.01 196.72,35.25 196.72,34.3 197.42,33.6 201.42,33.6 202.24,34.43 202.24,35.76
LX_DDR on TOP: 170.43,38.3 169.41,38.3 169.16,38.05 169.16,35.57 169.41,35.32 170.81,35.32 170.94,35.44 170.94,37.03 170.56,37.41 170.56,38.17
LX_DDR on BOTTOM: 171.71,39.43 173.79,37.35 175.26,37.35 175.45,37.16 175.45,35.95 175.32,35.82 172.78,35.82 172.65,35.7 168.27,35.7 167.19,36.78 167.19,39.33 167.3,39.43
LX_GT on TOP: 109.28,87.51 107.63,87.51 107.56,87.45 107.56,85.8 107.63,85.74 109.34,85.74 109.41,85.8 109.41,87.39
LX_GT on BOTTOM: 107.82,86.05 107.75,85.99 107.75,85.23 107.88,85.1 108.9,85.1 109.02,84.97 109.02,83.39 108.77,83.13 106.45,83.13 105.85,83.73 105.85,83.73 105.61,83.97 103.01,83.97 102.88,84.1 102.88,84.83 102.95,84.91 104.33,84.91 104.38,84.96 104.38,88.85 104.5,88.97 109.42,88.97 109.65,88.75 109.65,86.33 109.37,86.05
LX_SA on TOP: 199.19,112.02 197.73,112.02 197.61,111.9 197.61,110.37 197.73,110.25 199.26,110.25 199.39,110.37 199.39,111.83
LX_SA on BOTTOM: 196.53,110.18 197.54,110.18 197.54,109.29 196.34,109.29 196.27,109.23 196.27,107.96 196.4,107.83 199.26,107.83 199.58,108.15 199.58,113.17 200.66,114.25 200.66,114.75 200.34,115.07 196.65,115.07 196.59,115.14 196.59,116.34 196.53,116.41 195.77,116.41 195.7,116.34 195.7,114.31 196.46,113.55 196.46,110.25
NB_PSID on TOP (solid shape): 55.01,124.86 55.01,123.88 54.7,123.57 52.3,123.57 52.03,123.84 52.03,124.41 51.84,124.6 51.57,124.6 51.56,124.61 50.92,124.61 50.67,124.86 50.67,125.34 50.75,125.42 54.45,125.42
PANEL_PWRGD on TOP: 133.09,121.89 133.09,120.85 132.58,120.33 130.88,120.33 130.79,120.24 130.79,119.65 130.85,119.59 134.24,119.59 134.37,119.72 134.37,120.72 134.61,120.95 135.39,120.95 135.72,121.28 135.72,121.98 135.58,122.13 133.33,122.13
RING2 on TOP (solid shape): 284.74,52.21 284.74,49.24 284.61,49.11 284.22,49.11 284.09,49.24 284.09,50.59 284.45,50.95 284.45,51.1 284.48,51.13 284.48,52.21 284.55,52.27 284.67,52.27
RING2 on IN1 (solid shape): 284.6,50.63 284.6,48.22 284.28,47.9 283.52,47.9 283.27,48.16 283.27,50.19 283.84,50.76 284.48,50.76
RING2 on TOP: 295.78,34.36 294.83,34.36 294.64,34.17 294.64,32.46 294.7,32.4 295.78,32.4 295.91,32.52 295.91,34.24
RING2 on BOTTOM: 295.71,34.3 294.76,34.3 294.64,34.17 294.64,32.52 294.76,32.4 295.65,32.4 295.91,32.65 295.91,34.11
RING2 on IN1: 294.64,35.13 294.64,32.4 294.76,32.27 295.78,32.27 296.03,32.52 296.03,35.06 295.91,35.19 294.7,35.19
RING2_R on IN1 (solid shape): 314.99,40.42 314.99,39.11 314.69,38.81 313.34,38.81 313.16,38.99 313.16,39.93 313.04,40.05 304.91,40.05 303.64,38.78 303.64,37.01 304.12,36.52 304.12,32.94 303.65,32.46 302.7,32.46 302.41,32.75 302.41,39.61 303.39,40.59 314.83,40.59
RING2_R on IN2 (solid shape): 314.99,40.42 314.99,39.11 314.69,38.81 313.34,38.81 313.16,38.99 313.16,39.93 313.04,40.05 304.91,40.05 303.64,38.78 303.64,37.01 304.12,36.52 304.12,32.94 303.65,32.46 302.7,32.46 302.41,32.75 302.41,39.61 303.39,40.59 314.83,40.59
RING2_R on BOTTOM: 296.33,34.66 296.14,34.47 296.14,33.46 296.2,33.39 300.69,33.39 301.52,32.56 303.84,32.56 304.05,32.76 304.05,34.49 303.87,34.66
SLEEVE on TOP (solid shape): 285.12,51.13 285.49,50.76 285.49,49.24 285.36,49.11 285.05,49.11 284.92,49.24 284.92,50.82 284.92,50.83 284.92,52.24 285.12,52.24
SLEEVE on BOTTOM: 294.64,30.49 294.64,32.14 294.7,32.2 295.27,32.2 295.84,31.63 295.84,29.86 295.78,29.79 295.33,29.79
SLEEVE on IN4: 285.05,50.76 284.79,50.51 284.79,47.38 284.98,47.19 286.63,47.19 286.76,47.32 286.76,50.3 286.3,50.76
SLEEVE on IN4: 294.64,30.49 294.64,32.01 294.76,32.14 295.46,32.14 295.84,31.76 295.84,31.38 296.03,31.19 296.03,29.6 295.91,29.47 295.65,29.47
SLEEVE_R on IN3 (solid shape): 312.43,40.05 312.43,39.06 312.2,38.83 310.7,38.83 310.47,39.06 310.47,39.55 309.96,40.05 304.91,40.05 303.64,38.78 303.64,37.01 303.14,36.51 303.14,32.64 303.33,32.46 303.33,30.03 303.25,29.96 302.03,29.96 301.57,30.42 301.57,38.63 303.53,40.59 311.89,40.59
SLEEVE_R on IN4 (solid shape): 312.43,40.05 312.43,39.06 312.2,38.83 310.7,38.83 310.47,39.06 310.47,39.55 309.96,40.05 304.91,40.05 303.64,38.78 303.64,37.01 303.14,36.51 303.14,32.64 303.33,32.46 303.33,30.03 303.25,29.96 302.03,29.96 301.57,30.42 301.57,38.63 303.53,40.59 311.89,40.59
SLEEVE_R on BOTTOM: 301.35,31.84 300.44,30.93 297.05,30.93 296.98,30.87 296.98,30.62 296.79,30.43 296.22,30.43 296.16,30.36 296.16,29.78 296.23,29.71 303.12,29.71 303.33,29.91 303.33,31.7 303.18,31.84
SNUB1_CHG on TOP: 97.53,36.21 99.37,36.21 99.56,36.01 99.56,33.7 99.49,33.63 97.52,33.63 97.4,33.74 97.4,36.08
SNUB2_CHG on TOP: 108.39,38.05 105.79,38.05 105.66,37.92 105.66,36.4 105.72,36.33 107.37,36.33 107.44,36.4 107.44,36.97 107.63,37.16 108.45,37.16 108.52,37.22 108.52,37.92
SNUB_1.05VALWP on TOP (solid shape): 201.86,89.29 201.86,88.02 201.67,87.83 199.19,87.83 199.07,87.96 199.07,88.53 199.13,88.59 199.77,88.59 199.96,88.78 199.96,89.29 200.08,89.42 201.73,89.42
SNUB_1.8VALW on TOP (solid shape): 228.15,77.02 228.15,76.37 228.22,76.3 228.22,76.29 228.56,75.94 228.56,75.33 228.47,75.24 227.89,75.24 227.84,75.28 227.84,76.03 227.66,76.21 227.06,76.21 226.97,76.31 226.97,77.08 227.02,77.13 228.03,77.13
SNUB_1VS_VCCIO on BOTTOM: 193.21,101.74 193.66,101.28 194.05,100.89 194.05,99.58 193.99,99.51 193.48,99.51 193.35,99.64 193.35,100.59 193.1,100.85 192.21,100.85 192.15,100.91 192.15,101.67 192.21,101.74
SNUB_3V on TOP: 248.85,48.84 247.84,48.84 247.58,48.59 247.58,47 247.77,46.81 250.25,46.81 250.44,47 250.44,49.67 250.31,49.79 249.8,49.79
SNUB_5V on TOP: 205.99,33.92 205.99,32.9 205.93,32.84 205.16,32.84 204.72,33.28 203.39,33.28 203.32,33.35 203.32,34.3 203.45,34.43 205.48,34.43
SNUB_DDR on TOP: 172.46,37.16 174.3,37.16 174.56,36.9 174.56,35.36 174.45,35.26 172.5,35.26 172.4,35.35 172.4,37.09
UG1_CHG on BOTTOM (solid shape): 124.37,40.23 124.37,39.61 124.26,39.49 124.26,38.43 124.2,38.38 124.08,38.38 124.03,38.43 124.03,39.63 123.51,40.15 123.51,40.48 123.61,40.59 124.01,40.59
UG1_CHG on IN1 (solid shape): 124.5,41.18 124.5,39.94 124.24,39.68 124.05,39.68 122.93,40.8 122.93,41.54 123.19,41.79 123.88,41.79
UG1_CHG on BOTTOM: 101.15,39.44 102.23,39.44 102.36,39.32 102.36,38.11 102.23,37.98 101.21,37.98 101.02,38.17 101.02,39.32
UG1_CHG on IN1: 103.37,39.7 101.6,39.7 101.09,39.19 101.09,38.05 101.4,37.73 102.61,37.73 103.63,38.75 103.63,39.44
UG2_CHG on BOTTOM (solid shape): 122.22,37.08 123.11,37.08 123.16,37.03 123.16,36.9 123.11,36.85 122.07,36.85 121.89,36.67 121.49,36.67 121.33,36.52 121.11,36.52 121,36.62 121,37.03 121.11,37.13 122.17,37.13
UG2_CHG on TOP: 116.2,31.51 115.12,31.51 114.99,31.38 114.99,30.43 115.06,30.36 116.2,30.36 116.33,30.49 116.33,31.38
UG2_CHG on IN1: 122.08,37.02 122.08,35.8 121.72,35.44 120.52,35.44 120.31,35.66 120.31,36.8 120.65,37.14 121.96,37.14
UG2_CHG on IN1: 115.79,31.57 116.26,31.57 117.03,32.33 118.85,32.33 118.96,32.23 118.96,31.54 118.42,31.01 117.83,31.01 117.25,30.43 115.85,30.43 115.72,30.55 115.72,31.51
VOUT_1.2V_RUN on BOTTOM (solid shape): 271.12,64.32 270.56,64.32 270.56,63.81 271.12,63.81 271.12,62.32 270.81,62.01 269.72,62.01 269.47,61.76 269.47,60.74 268.96,60.74 268.96,62.39 268.63,62.72 268.63,63.61 268.73,63.71 269.36,63.71 270.2,64.55 271.12,64.55
VOUT_2.5V_MEM on TOP: 145.18,38.22 146.71,38.22 147.15,37.78 147.15,35.75 146.96,35.56 144.74,35.56 144.67,35.49 144.67,33.97 144.55,33.84 143.98,33.84 143.85,33.97 143.85,38.03 144.04,38.22 144.67,38.22 144.67,37.65 145.18,37.65
VTTREF_DDR on BOTTOM: 176.14,35.7 176.33,35.7 176.4,35.63 176.4,34.68 176.65,34.43 176.65,33.6 176.59,33.54 175.7,33.54 175.64,33.6 175.64,34.05 175.7,34.11 175.89,34.11 176.08,34.3 176.08,34.62 176.02,34.68 176.02,35.57
N16783222 on BOTTOM: 200.91,39.51 201.42,39.51 201.54,39.38 201.54,37.03 201.1,36.59 200.4,36.59 200.27,36.71 200.27,37.28 200.78,37.79 200.78,39.38
N17370862 on TOP: 74.54,122.88 75.94,122.88 76,122.82 76,120.72 76.13,120.6 76.96,120.6 77.21,120.34 77.21,119.14 77.02,118.95 75.37,118.95 75.12,119.2 75.12,120.85 75.31,121.04 75.31,122.06 75.24,122.12 74.48,122.12 74.42,122.18 74.42,122.76
N17370862 on BOTTOM: 75.62,120.53 74.99,120.53 74.93,120.47 74.93,119.39 75.05,119.26 75.69,119.26 75.75,119.33 75.75,120.41
N17370885 on TOP: 76.39,118.5 76.7,118.18 76.7,117.1 77.53,116.28 77.53,115.71 77.4,115.58 76.45,115.58 76.2,115.83 76.2,116.47 76.08,116.58 75.42,116.58 74.99,117.02 74.99,118.31 75.18,118.5
N17371029 on BOTTOM: 70.8,127.71 71.37,127.71 71.43,127.65 71.43,126.76 71.56,126.63 72.7,126.63 72.89,126.44 72.89,125.99 72.77,125.87 71.81,125.87 71.5,126.18 69.91,126.18 69.85,126.25 69.85,126.82 69.91,126.88 70.54,126.88 70.73,127.07 70.73,127.65
N25591872 on TOP: 100.41,130.79 100.41,128.42 100.57,128.25 100.96,128.25 101.12,128.42 101.12,130.78 101.07,130.84 100.46,130.84
N25736614 on TOP (solid shape): 230.86,73.15 230.86,72.34 231.24,71.97 231.89,71.97 231.94,71.91 231.94,71.43 231.81,71.3 230.31,71.3 230.06,71.55 230.06,73.15 230.25,73.34 230.68,73.34
N25908024 on BOTTOM: 75.62,114.12 75.5,113.99 75.5,111.68 74.94,111.12 74.94,109.19 75.22,108.91 75.98,108.91 76.21,109.14 76.21,109.57 76.49,109.86 77.65,109.86 78.23,110.44 78.23,111.9 78.1,112.02 77.27,112.02 77.08,112.21 77.08,113.93 76.89,114.12
N25908122 on TOP: 74.2,123.9 74.42,123.68 74.95,123.68 75.22,123.42 75.22,123.14 75.07,122.98 73.68,122.98 73.26,122.56 72.67,122.56 72.58,122.66 72.58,124.43 72.73,124.58 72.73,125.73 72.83,125.82 73.72,125.82 74.2,125.35
N25908152 on TOP: 77.97,123.9 77.97,123.89 77.83,123.89 77.76,123.82 77.76,123.31 77.99,123.09 77.99,121.38 78.14,121.23 78.65,121.23 78.8,121.38 78.8,123.77 78.67,123.9
N27521746 on TOP: 164.21,123.58 164.21,122.12 164.33,121.99 165.92,121.99 167,123.07 167,123.64 166.81,123.84 164.46,123.84
N27522693 on TOP: 182.18,123.39 182.3,123.52 182.3,124.66 182.24,124.72 179.64,124.72 179.57,124.66 179.57,123.45 179.64,123.39
N27523201 on TOP: 172.84,124.85 171.25,124.85 171,124.6 170.24,124.6 170.18,124.53 170.18,123.71 170.24,123.64 172.91,123.64 172.97,123.71 172.97,124.72
N27523847 on TOP: 194.31,122.95 192.72,122.95 192.59,122.82 192.59,121.8 192.72,121.68 195.32,121.68 195.45,121.8 195.45,122.63 195.38,122.69 194.56,122.69
N27524640 on TOP: 106.04,87.58 105.02,87.58 104.9,87.45 104.9,84.78 104.96,84.72 105.98,84.72 106.1,84.85 106.1,87.51
N27525287 on TOP: 198.37,115.01 199.26,115.01 199.45,114.82 199.45,112.98 199.39,112.91 197.61,112.91 197.54,112.98 197.54,113.93 197.67,114.06 198.18,114.06 198.31,114.18 198.31,114.95
N27715583 on TOP (solid shape): 39.93,124.85 39.93,124.26 39.9,124.18 39.83,124.15 39.55,124.01 39.49,123.71 39.49,123.7 39.49,123.55 39.38,123.44 39.38,123.24 39.41,123.21 39.41,122.62 39.31,122.53 39.09,122.53 38.56,123.06 37.74,123.06 37.6,123.2 37.6,123.63 37.9,123.93 37.9,125.22 37.99,125.31 39.47,125.31
N27715644 on TOP (solid shape): 39.91,121.84 39.91,120.51 40.83,119.59 40.83,119.24 40.31,118.72 39.63,118.72 39.57,118.78 39.57,121.83 39.63,121.89 39.86,121.89
N27715680 on TOP (solid shape): 39.41,121.83 39.41,121.02 39.3,120.91 38,120.91 37.37,120.28 34.81,120.28 34.72,120.37 34.72,121.56 34.98,121.83 36.65,121.83 36.71,121.88 39.36,121.88
N27715838 on IN1: 47.43,122.89 44.54,122.89 43.71,122.05 43.71,120.35 44.35,119.71 46.79,119.71 47.43,120.35
N27715969 on TOP (solid shape): 43.95,124.16 43.95,123.47 43.84,123.36 43.6,123.36 43.58,123.34 43.07,123.34 42.76,123.04 41.42,123.04 41.38,123.08 41.38,123.56 41.64,123.82 41.66,123.82 42.07,124.23 43.88,124.23
N27884552 on TOP: 126.76,43.45 126.76,39.64 127.06,39.34 128.33,39.34 129.9,40.9 133.41,40.9 133.62,41.11 133.62,42.9 133.5,43.03 128.18,43.03 127.7,43.5 126.81,43.5
N31929169 on TOP: 115.08,133.56 114.75,133.23 113.27,133.23 113.09,133.04 113.09,132.34 113.34,132.09 115.39,132.09 115.82,132.52 120.99,132.52 121.49,133.02 121.49,134.67 121.36,134.79 117.85,134.79 117.64,134.58 117.64,133.67 117.53,133.56
N35445396 on TOP: 143.89,123.71 143.95,123.64 144.65,123.64 145.47,124.47 145.47,127.3 145.32,127.45 144.33,127.45 143.89,127.01
N35445635 on TOP: 143.55,124.34 142.9,124.34 142.58,124.03 142.58,120.37 142.87,120.09 144.84,120.09 145.16,120.41 145.16,121.84 143.66,123.33 143.66,124.23

Small or netless copper shapes (teardrops, artwork), in the pictures only: 194 on TOP, 31 on BOTTOM

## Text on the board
Ref Des/Silkscreen Bottom: M2X3 | IR/TS | EDP | BATT CONN | KB/TP | USH | SATA HDD | SSD | WWAN/LTE/SSD | SPKR | WLAN/BT | RTC | LED | DC IN | FAN | DDR4 | DIMM A | REV:A00 | PWB P/N:J11RG | ALL RIGHT RESERVED | COPYRIGHT 2019 | DIMM B
User.Comments: LA-H171P | 2020-03-21 | 2019-03-21 | Minjia_Cai | EDC42 | 1.0(A00)
BODY_CENTER: LAYER | NO. | L1 | L2 | L3 | L4 | L5 | L6 | L7 | L8 | L9 | L10 | LA-H171P | VCC | GND2 | TOP | GND1 | IN1 | BOT | GND3 | IN2 | IN3 | IN4
User.15: LAYER | NO. | L1 | L2 | L3 | L10 | L9 | L4 | L5 | L6 | L7 | L8 | LA-H171P | GND2 | GND3 | GND1 | IN4 | TOP | IN1 | IN3 | BOT | IN2 | VCC | DUMMY COPPER | LS-G891P | Secret Level | Issued | Decipherment date | BOARD Thickness(mm) | PROJECT | DRAW BY | BOARD NO. | Date | COMPAL ELECTRONICS. INC. | Secret data | REV: | 226.9 | 228.9 | -3 | -5 | 209.9 | 211.4 | 168.6 | 134 | 163.9 | X:20.47 | Y:165.21 | X:30.58 | Y:149.18 | 6 | 216.4 | 217.9 | 222.9 | X:48.24 | Y:177.69 | 155.9 | 148.9 | 115.5 | X:72.95 | Y:176.37 | X:89.51 | Y:130.28 | Print white paint on BOT silkscreen | Print white paint on TOP silkscreen | 0 | 223.9 | X:235.54 | Y:93.62 | 108.4 | X:252.1 | Y:47.43 | 68 | 75 | REV:0.3 | (TOP) | X:276.81 | Y:46.21 | 1 | X:304.58 | Y:58.69 | 7.5 | X:294.47 | Y:74.72 | 60 | 89.9 | 55.3 | 14 | 12.5 | ZORA-ZHU | 2019-01-14 | 2020-01-14 | 1.2 | EDC42 | 10% | 0.4 | 0.3 | -4 | 10.7 | 12.05 | 11.05 | 13.55 | 18.55 | 20.05 | 22.05 | 43.05 | 42 | 44 | 53.05 | 53 | 78 | 106.05 | 116.03 | 120 | 150.05 | 162.53 | 175 | 205.05 | 209.03 | 219 | 247.05 | 272 | 272.05 | 281.05 | 283.05 | 282 | 303 | 305 | 306.5 | 311.5 | 314 | 313 | 314.35 | 324.05 | 325.05 | 329.05 | R3X4 | R5X4 | Tooling Hole:2mm x3 | Tooling Hole:2.7mm(+/-1.5mil) x4 | Barcode area:8X8 on top side onlyX2 | Notes: | 1.To Use 2mm(min) router | for breakaway | 2.Refer to detail 2M,4M,8M, | 10M for TAB spec. | REV:0.4(TOP) | 0.127mm | F | 333.05 | 233.9
User.42: IMPEDANCE
User.44: Width/space | 7.1 / 3.5 | L8 | L3 | 90 ohm | Ref
User.45: FIGURE | SIZE | 8.0 | 22.0 | 28.0 | 35.0 | 102.0 | 118.0 | 126.0 | 130.0 | 150.0 | 157.0 | 30.0 | 31.0 | 43.0 | 63.0 | 71.0 | 83.0 | 87.0 | 197.0 | 47.0x20.0 | 49.0x28.0 | 55.0x24.0 | 55.0x39.0 | 71.0x28.0 | 75.0x24.0 | 79.0x24.0 | 79.0x28.0 | 87.0x39.0 | 33.0x28.0 | 98.0x83.0 | 122.0x83.0 | DRILL CHART: TOP to BOTTOM | ALL UNITS ARE IN MILS | TOLERANCE | +3.0/-3.0 | +2.0/-2.0 | PLATED | NON-PLATED | QTY | 8129 | 19 | 27 | 8 | 4 | 1 | 2 | 3 | 5 | 7 | 12
